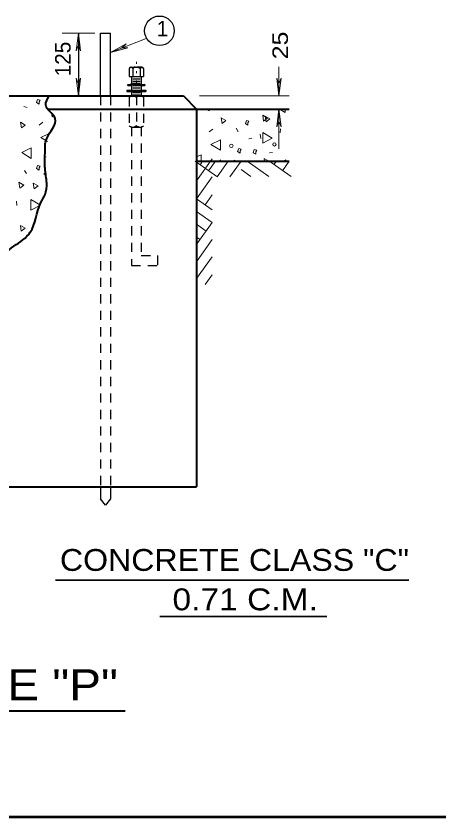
# Model space of a CAD drawing. Extents: x 312583 to 312854, y 144419 to 144597.
# Drawn here: x 312763.3 to 312784.05, y 144504.05 to 144543.31 of the extents above; entities that cross this region are included whole.
import ezdxf
from ezdxf.enums import TextEntityAlignment as Align

# ---------------------------------------------------------------- set-up
doc = ezdxf.new("R2010")
doc.units = 0
doc.header["$LTSCALE"] = 0.3
doc.linetypes.add('DOTTED', pattern=[1.5, 0.3, -1.2])
doc.linetypes.add('SHORT_DASHED', pattern=[2.7, 1.5, -1.2])
doc.layers.add('1', color=7, linetype='Continuous', lineweight=25)
doc.layers.add('2', color=7, linetype='Continuous', lineweight=13)

msp = doc.modelspace()

# ---------------------------------------------------------------- linework, layer by layer
at = {"layer": '1', "linetype": 'DOTTED', "lineweight": 13}
msp.add_line((312769.2114, 144541.0728), (312769.2114, 144539.3938), dxfattribs=at)
at = {"layer": '1'}
for p, q in [((312768.851, 144540.7431), (312768.851, 144540.3521)), ((312768.943, 144540.8044), (312769.4797, 144540.8044)), ((312769.0274, 144540.7431), (312769.0274, 144540.3521)), ((312769.3877, 144540.7431), (312769.3877, 144540.3521)), ((312769.564, 144540.7431), (312769.564, 144540.3521)), ((312768.851, 144540.3521), (312769.564, 144540.3521)), ((312768.966, 144540.3521), (312768.966, 144539.3938)), ((312769.0274, 144540.2371), (312769.3877, 144540.2371)), ((312769.0274, 144540.1221), (312769.3877, 144540.1221)), ((312769.449, 144540.3521), (312769.449, 144539.3938)), ((312768.7897, 144539.9534), (312768.7897, 144539.8998)), ((312769.0274, 144540.0148), (312769.3877, 144540.0148)), ((312769.0274, 144539.8998), (312769.3877, 144539.8998)), ((312769.0274, 144539.7848), (312769.3877, 144539.7848)), ((312769.173, 144539.8998), (312769.6254, 144539.8998)), ((312769.1884, 144539.9534), (312769.6254, 144539.9534)), ((312769.6254, 144539.9534), (312769.6254, 144539.8998)), ((312768.736, 144539.6774), (312769.679, 144539.6774)), ((312768.736, 144539.6774), (312768.736, 144539.6161)), ((312768.736, 144539.6621), (312769.679, 144539.6621)), ((312768.736, 144539.6468), (312769.679, 144539.6468)), ((312768.736, 144539.6314), (312769.679, 144539.6314)), ((312768.736, 144539.6161), (312769.679, 144539.6161)), ((312769.0274, 144539.5624), (312769.3877, 144539.5624)), ((312769.0274, 144539.4474), (312769.3877, 144539.4474)), ((312769.679, 144539.6774), (312769.679, 144539.6161))]:
    msp.add_line(p, q, dxfattribs=at)
at = {"layer": '1', "lineweight": 40}
for p, q in [((312740.86, 144539.3938), (312771.5267, 144539.3938)), ((312771.5267, 144539.3938), (312772.163, 144538.7498)), ((312764.9027, 144538.7498), (312776.7017, 144538.7498)), ((312772.163, 144538.7498), (312772.163, 144520.2271)), ((312772.163, 144536.1968), (312776.7017, 144536.1968)), ((312740.216, 144520.2271), (312772.163, 144520.2271))]:
    msp.add_line(p, q, dxfattribs=at)
at = {"layer": '1', "linetype": 'SHORT_DASHED'}
for p, q in [((312767.448, 144539.3938), (312767.448, 144520.2271)), ((312767.931, 144539.3938), (312767.931, 144520.2271)), ((312768.966, 144539.3938), (312769.449, 144539.3938)), ((312769.035, 144539.3938), (312769.38, 144539.3938)), ((312769.2114, 144539.3938), (312769.2114, 144537.8681)), ((312768.8587, 144539.3324), (312768.8587, 144537.9294)), ((312769.5564, 144539.3324), (312769.5564, 144537.9294)), ((312769.5564, 144538.4508), (312769.5717, 144538.4431)), ((312768.966, 144537.8681), (312768.966, 144531.0831)), ((312769.035, 144537.8681), (312769.38, 144537.8681)), ((312769.449, 144537.8681), (312769.449, 144531.5661)), ((312768.966, 144531.0831), (312770.2464, 144531.0831))]:
    msp.add_line(p, q, dxfattribs=at)
at = {"layer": '1'}
for points in [[(312768.9584, 144540.8044), (312769.1654, 144540.7968), (312769.127, 144540.7968), (312769.104, 144540.7891), (312769.0657, 144540.7738), (312769.0274, 144540.7508), (312769.0197, 144540.7738), (312768.9967, 144540.7814), (312768.9737, 144540.7968), (312769.1424, 144540.7968), (312769.0964, 144540.7891), (312769.058, 144540.7738), (312769.035, 144540.7508), (312769.0044, 144540.7814), (312768.9814, 144540.7968), (312769.127, 144540.7968), (312769.0734, 144540.7814), (312769.035, 144540.7584), (312768.989, 144540.7968), (312769.1117, 144540.7968), (312769.0274, 144540.7661), (312768.9967, 144540.7891), (312769.0964, 144540.7968), (312769.0274, 144540.7661), (312769.0044, 144540.7891), (312769.081, 144540.7891), (312769.0274, 144540.7738), (312769.012, 144540.7891), (312769.058, 144540.7891), (312769.035, 144540.7738), (312769.0274, 144540.7814), (312769.0427, 144540.7814), (312769.035, 144540.7814)], [(312769.4567, 144540.8044), (312769.2497, 144540.7968), (312769.288, 144540.7968), (312769.311, 144540.7891), (312769.3494, 144540.7738), (312769.3877, 144540.7508), (312769.3954, 144540.7738), (312769.4184, 144540.7814), (312769.449, 144540.7968), (312769.2727, 144540.7968), (312769.3187, 144540.7891), (312769.357, 144540.7738), (312769.38, 144540.7508), (312769.4107, 144540.7814), (312769.4337, 144540.7968), (312769.288, 144540.7968), (312769.3417, 144540.7814), (312769.38, 144540.7584), (312769.426, 144540.7968), (312769.311, 144540.7968), (312769.3877, 144540.7661), (312769.4184, 144540.7891), (312769.3187, 144540.7968), (312769.3877, 144540.7661), (312769.4107, 144540.7891), (312769.334, 144540.7891), (312769.3877, 144540.7738), (312769.403, 144540.7891), (312769.357, 144540.7891), (312769.38, 144540.7738), (312769.3877, 144540.7814), (312769.3724, 144540.7814), (312769.3877, 144540.7814)], [(312768.7897, 144539.9534), (312769.2114, 144540.0148), (312769.173, 144539.8998)], [(312769.1884, 144539.9534), (312768.7897, 144539.8998), (312768.966, 144539.8998)], [(312768.966, 144539.8998), (312768.7974, 144539.9074), (312768.7974, 144539.9534), (312769.196, 144540.0071), (312769.1807, 144539.9611), (312768.966, 144539.9304), (312768.9584, 144539.9074), (312768.805, 144539.9151), (312768.805, 144539.9458), (312769.1884, 144539.9994), (312769.1807, 144539.9688), (312768.9584, 144539.9304), (312768.9507, 144539.9151), (312768.8127, 144539.9228), (312768.8127, 144539.9381), (312769.173, 144539.9841), (312769.173, 144539.9764), (312768.9584, 144539.9381), (312768.943, 144539.9304), (312768.897, 144539.9228), (312768.8204, 144539.9228), (312769.1577, 144539.9764), (312768.874, 144539.9228)], [(312769.1807, 144539.9074), (312769.6177, 144539.9074), (312769.6177, 144539.9534), (312769.196, 144539.9458), (312769.1807, 144539.9151), (312769.61, 144539.9151), (312769.61, 144539.9458), (312769.2037, 144539.9381), (312769.196, 144539.9228), (312769.6024, 144539.9228), (312769.5947, 144539.9304), (312769.5947, 144539.9381), (312769.2037, 144539.9304), (312769.196, 144539.9228), (312769.587, 144539.9304)]]:
    msp.add_lwpolyline(points, dxfattribs=at)
at = {"layer": '1', "linetype": 'SHORT_DASHED'}
for points in [[(312769.081, 144539.3861), (312769.3417, 144539.3938), (312769.311, 144539.3861), (312769.2804, 144539.3784), (312769.2497, 144539.3631), (312769.2344, 144539.3554), (312769.2114, 144539.3401), (312769.2114, 144539.3324), (312769.1577, 144539.3631), (312769.1194, 144539.3784), (312769.0887, 144539.3861), (312769.3187, 144539.3861), (312769.3034, 144539.3861), (312769.2804, 144539.3784), (312769.2497, 144539.3708), (312769.2267, 144539.3554), (312769.219, 144539.3478), (312769.2037, 144539.3401), (312769.1654, 144539.3708), (312769.1194, 144539.3861), (312769.288, 144539.3861), (312769.242, 144539.3708), (312769.2114, 144539.3478), (312769.1347, 144539.3861), (312769.2727, 144539.3861), (312769.2114, 144539.3478), (312769.15, 144539.3784), (312769.2574, 144539.3784), (312769.2114, 144539.3554), (312769.173, 144539.3784), (312769.242, 144539.3784), (312769.2114, 144539.3631), (312769.173, 144539.3708), (312769.196, 144539.3554), (312769.196, 144539.3708), (312769.2037, 144539.3478), (312769.219, 144539.3708), (312769.2344, 144539.3708), (312769.242, 144539.3708)], [(312769.081, 144537.8681), (312769.3417, 144537.8681), (312769.311, 144537.8758), (312769.2804, 144537.8834), (312769.2497, 144537.8911), (312769.2344, 144537.9064), (312769.2114, 144537.9218), (312769.2114, 144537.9218), (312769.1577, 144537.8911), (312769.1194, 144537.8758), (312769.0887, 144537.8681), (312769.3187, 144537.8681), (312769.3034, 144537.8681), (312769.2804, 144537.8758), (312769.2497, 144537.8834), (312769.2267, 144537.8988), (312769.219, 144537.9064), (312769.2037, 144537.9218), (312769.1654, 144537.8911), (312769.1194, 144537.8758), (312769.288, 144537.8681), (312769.242, 144537.8834), (312769.2114, 144537.9064), (312769.1347, 144537.8758), (312769.2727, 144537.8758), (312769.2114, 144537.9141), (312769.15, 144537.8758), (312769.2574, 144537.8758), (312769.2114, 144537.8988), (312769.173, 144537.8834), (312769.242, 144537.8834), (312769.2114, 144537.8911), (312769.173, 144537.8834), (312769.196, 144537.8988), (312769.196, 144537.8834), (312769.2037, 144537.9064), (312769.219, 144537.8911), (312769.2344, 144537.8911), (312769.242, 144537.8834)], [(312769.449, 144531.5661), (312770.2464, 144531.5661), (312770.2464, 144531.0831)]]:
    msp.add_lwpolyline(points, dxfattribs=at)
at = {"layer": '1'}
for centre, radius, start, end in [((312768.9389, 144540.7029), 0.0993, 25.60064, 154.39936), ((312769.2075, 144540.4896), 0.3126, 55.04559, 124.95441), ((312769.4762, 144540.7029), 0.0993, 25.60064, 154.39936)]:
    msp.add_arc(centre, radius, start, end, dxfattribs=at)
at = {"layer": '1', "linetype": 'SHORT_DASHED'}
for centre, start, end in [((312769.0327, 144539.1204), 50.00693, 129.99306), ((312769.3823, 144539.1204), 50.00694, 129.99307), ((312769.0327, 144538.1378), 230.00694, 309.99307), ((312769.3823, 144538.1378), 230.00693, 309.99306)]:
    msp.add_arc(centre, 0.272, start, end, dxfattribs=at)
at = {"layer": '1', "lineweight": 40}
msp.add_spline([(312747.07, 144539.3938), (312747.4074, 144536.8408), (312748.0437, 144535.6218), (312748.887, 144535.3688), (312749.393, 144535.1541), (312750.8727, 144534.0578), (312751.0874, 144533.5518), (312751.1717, 144533.3371), (312751.509, 144532.4938), (312752.0534, 144531.9418), (312752.4367, 144531.5201), (312753.28, 144531.2671), (312754.085, 144531.2671), (312755.4727, 144531.3974), (312756.1474, 144531.4818), (312757.5044, 144531.1828), (312758.3477, 144531.0141), (312759.8657, 144531.1828), (312760.9237, 144531.1444), (312762.2347, 144531.3974), (312763.2007, 144532.0261), (312764.0057, 144532.7084), (312764.5117, 144534.1421), (312764.7264, 144534.5638), (312764.8107, 144535.1158), (312764.7264, 144535.8288), (312764.7264, 144536.5878), (312764.8107, 144537.3084), (312765.2324, 144538.2821), (312764.7647, 144538.9568), (312764.9334, 144539.3938)], degree=3, dxfattribs=at)
at = {"layer": '2'}
for p, q in [((312767.1644, 144542.4758), (312765.562, 144542.4758)), ((312766.367, 144542.4758), (312766.2597, 144541.6094)), ((312766.367, 144542.4758), (312766.4744, 144541.6094)), ((312769.6944, 144542.2151), (312767.9387, 144541.5251)), ((312766.2597, 144541.6094), (312766.367, 144541.8854)), ((312766.4744, 144541.6094), (312766.367, 144541.8854)), ((312767.9464, 144541.5251), (312768.713, 144541.9544)), ((312767.9464, 144541.5251), (312768.7897, 144541.7551)), ((312768.713, 144541.9544), (312768.4907, 144541.7474)), ((312768.7897, 144541.7551), (312768.4907, 144541.7474)), ((312776.2034, 144539.3938), (312776.2034, 144540.8274)), ((312766.2597, 144540.2601), (312766.367, 144539.9841)), ((312766.367, 144539.3938), (312766.2597, 144540.2601)), ((312766.4744, 144540.2601), (312766.367, 144539.9841)), ((312766.367, 144539.3938), (312766.4744, 144540.2601)), ((312776.096, 144540.2601), (312776.2034, 144539.9841)), ((312776.2034, 144539.3938), (312776.096, 144540.2601)), ((312776.3107, 144540.2601), (312776.2034, 144539.9841)), ((312776.2034, 144539.3938), (312776.3107, 144540.2601)), ((312768.0077, 144539.4014), (312768.023, 144539.3938)), ((312768.2837, 144539.3938), (312768.2837, 144539.4014)), ((312772.3087, 144539.3938), (312776.7017, 144539.3938)), ((312763.6837, 144538.8801), (312763.8524, 144538.8341)), ((312765.0407, 144538.5964), (312765.0714, 144538.3664)), ((312776.2034, 144538.7498), (312776.096, 144537.8834)), ((312776.2034, 144536.7948), (312776.2034, 144538.7498)), ((312776.2034, 144538.7498), (312776.3107, 144537.8834)), ((312776.2264, 144538.7498), (312776.51, 144538.5811)), ((312776.51, 144538.5811), (312776.51, 144538.7498)), ((312765.0714, 144538.3664), (312765.1557, 144538.4354)), ((312772.163, 144538.5121), (312772.1937, 144538.4968)), ((312776.096, 144537.8834), (312776.2034, 144538.1594)), ((312776.3107, 144537.8834), (312776.2034, 144538.1594)), ((312764.619, 144538.1058), (312764.4427, 144537.9678)), ((312772.9604, 144537.7684), (312772.784, 144537.6381)), ((312774.1104, 144537.8144), (312774.2024, 144537.6381)), ((312776.257, 144537.5921), (312776.28, 144537.7838)), ((312775.2834, 144537.5154), (312775.3064, 144537.3084)), ((312774.7237, 144537.2854), (312774.8694, 144537.3238)), ((312775.7434, 144536.6108), (312775.889, 144536.6184)), ((312764.7187, 144536.3961), (312764.78, 144536.4038)), ((312773.152, 144535.4378), (312772.0864, 144536.1968)), ((312772.922, 144536.3041), (312772.163, 144535.2384)), ((312773.244, 144536.1968), (312773.359, 144536.2658)), ((312775.705, 144535.4378), (312774.6394, 144536.1968)), ((312776.7937, 144535.4378), (312775.705, 144536.2121)), ((312776.0807, 144536.1968), (312775.958, 144536.0281)), ((312776.7094, 144536.1968), (312776.3797, 144535.7291)), ((312772.4544, 144536.1891), (312772.3394, 144536.0204)), ((312773.083, 144536.1891), (312772.7534, 144535.7214)), ((312773.7117, 144536.1891), (312773.1674, 144535.4224)), ((312774.3404, 144536.1891), (312773.796, 144535.4224)), ((312763.7144, 144535.7368), (312763.8217, 144535.5988)), ((312772.922, 144535.4301), (312772.163, 144534.3568)), ((312774.8234, 144535.4378), (312774.3404, 144535.7828)), ((312763.3234, 144534.2341), (312763.3464, 144534.0271)), ((312772.163, 144534.3568), (312772.922, 144533.8124)), ((312772.922, 144534.5484), (312772.577, 144534.0578)), ((312772.163, 144533.7281), (312772.922, 144533.1914)), ((312772.922, 144533.1914), (312772.1477, 144532.1028)), ((312772.163, 144533.1071), (312772.6307, 144532.7698)), ((312772.163, 144532.4784), (312772.3317, 144532.3558)), ((312772.922, 144532.3558), (312772.186, 144531.3131)), ((312772.922, 144531.5124), (312772.163, 144530.4468)), ((312772.922, 144530.6308), (312772.577, 144530.1478))]:
    msp.add_line(p, q, dxfattribs=at)
at = {"layer": '2', "lineweight": 25}
for p, q in [((312766.367, 144542.4758), (312766.367, 144539.3938)), ((312767.448, 144542.4758), (312767.931, 144542.4758)), ((312767.448, 144539.3938), (312767.448, 144542.4758)), ((312767.931, 144539.3938), (312767.931, 144542.4758)), ((312767.448, 144520.2271), (312767.448, 144519.6521))]:
    msp.add_line(p, q, dxfattribs=at)
at = {"layer": '2', "lineweight": 35}
for p, q in [((312765.2373, 144515.6517), (312782.5716, 144515.6517)), ((312770.3582, 144513.873), (312778.548, 144513.873))]:
    msp.add_line(p, q, dxfattribs=at)
at = {"layer": '2', "lineweight": 40}
msp.add_line((312742.0746, 144509.2465), (312768.666, 144509.2465), dxfattribs=at)
at = {"layer": '2', "lineweight": 53}
msp.add_line((312708.1809, 144504.0495), (312849, 144504.0495), dxfattribs=at)
at = {"layer": '2'}
for points in [[(312764.435, 144539.1024), (312764.481, 144539.1791), (312764.366, 144539.2174), (312764.3047, 144539.0641), (312764.435, 144538.9951)], [(312773.4127, 144538.0368), (312773.6044, 144538.1824), (312773.3744, 144538.3204)], [(312774.6777, 144538.0751), (312774.7237, 144538.1518), (312774.6087, 144538.1901), (312774.555, 144538.0368), (312774.6777, 144537.9678)], [(312775.4444, 144538.1594), (312775.636, 144538.3051), (312775.406, 144538.4508)], [(312775.567, 144538.1211), (312775.7587, 144538.2668), (312775.5287, 144538.4048)], [(312763.5687, 144537.8221), (312763.7604, 144537.9678), (312763.5304, 144538.1134)], [(312775.406, 144537.5998), (312775.406, 144537.0784), (312775.8737, 144537.3161)], [(312773.336, 144536.7334), (312773.336, 144537.2471), (312772.8684, 144537.0171)], [(312764.0517, 144536.3348), (312764.0517, 144536.8484), (312763.584, 144536.6184)], [(312774.302, 144536.7028), (312774.348, 144536.7794), (312774.233, 144536.8178), (312774.1717, 144536.6644), (312774.302, 144536.5954)], [(312775.0687, 144536.6491), (312775.1147, 144536.7334), (312774.992, 144536.7641), (312774.9384, 144536.6108), (312775.0687, 144536.5418)], [(312764.4427, 144535.8671), (312764.4887, 144535.9514), (312764.366, 144535.9821), (312764.3124, 144535.8364), (312764.4427, 144535.7598)], [(312763.4844, 144534.8781), (312763.6837, 144535.0238), (312763.446, 144535.1694)], [(312764.1897, 144534.8398), (312764.389, 144534.9854), (312764.1514, 144535.1234)], [(312764.0364, 144534.3108), (312764.0364, 144533.7971), (312764.504, 144534.0348)], [(312763.561, 144532.7621), (312763.7527, 144532.9078), (312763.5227, 144533.0458)]]:
    msp.add_lwpolyline(points, close=True, dxfattribs=at)
for points in [[(312772.6537, 144538.7498), (312772.646, 144538.7268), (312772.7764, 144538.6578), (312772.7764, 144538.7498)], [(312764.9027, 144537.5384), (312764.527, 144537.3544), (312764.849, 144537.1551)], [(312772.393, 144536.1968), (312772.393, 144536.5111), (312772.163, 144536.4038)], [(312774.0874, 144536.1968), (312774.003, 144536.2504), (312774.0107, 144536.1968)], [(312775.6974, 144536.1968), (312775.4827, 144536.3271), (312775.498, 144536.1968)], [(312776.5407, 144536.1968), (312776.5407, 144536.2658), (312776.4104, 144536.1968)], [(312764.7494, 144535.6218), (312764.6727, 144535.5834), (312764.757, 144535.5298)]]:
    msp.add_lwpolyline(points, dxfattribs=at)
at = {"layer": '2', "lineweight": 25}
msp.add_lwpolyline([(312767.931, 144520.2271), (312767.931, 144519.6521), (312767.6934, 144519.3301), (312767.448, 144519.6521)], dxfattribs=at)
msp.add_circle((312770.3396, 144542.5857), 0.7254, dxfattribs=at)
at = {"layer": '2'}
for centre, radius in [((312773.8675, 144536.9459), 0.0865), ((312775.9807, 144537.0164), 0.0784)]:
    msp.add_circle(centre, radius, dxfattribs=at)

# ---------------------------------------------------------------- texts
msp.add_text('1', height=0.76, dxfattribs=at).set_placement((312770.2059, 144542.3112))
at = {"layer": '2', "width": 1.2}
msp.add_text('25  ', height=0.76, rotation=90, dxfattribs=at).set_placement((312776.6425, 144541.1902))
at = {"layer": '2'}
msp.add_text('125', height=0.76, rotation=90, dxfattribs=at).set_placement((312765.9818, 144540.3558))
for s, height, width, p in [('CONCRETE CLASS "C"', 1.07, 1.1, (312774.0207, 144516.1134)), ('0.71 C.M.', 1.07, 1.15, (312774.5456, 144514.1814)), ('FOUNDATION TYPE "P"', 1.52, 1.15, (312755.2659, 144509.7732))]:
    msp.add_text(s, height=height, dxfattribs=dict(at, width=width)).set_placement(p, align=Align.CENTER)

doc.saveas('drawing.dxf')
